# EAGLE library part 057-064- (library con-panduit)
CONNECTOR 64-pin series 057 contact pc board low profile headers
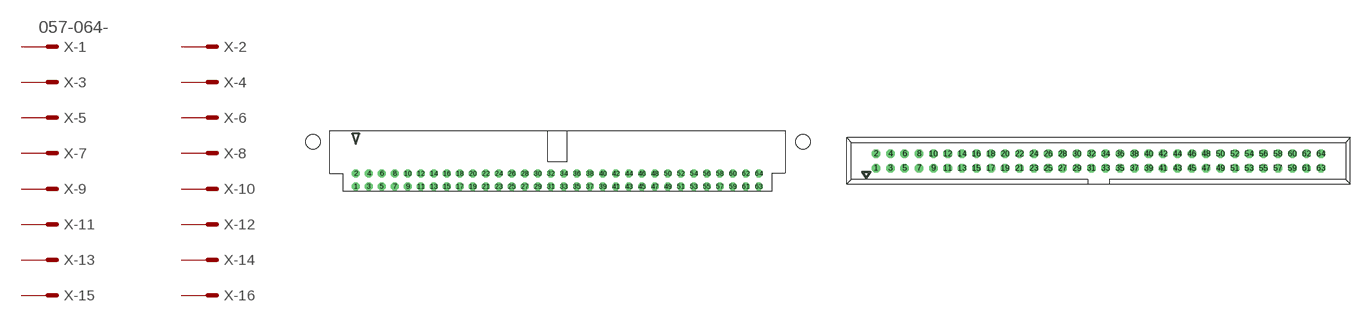
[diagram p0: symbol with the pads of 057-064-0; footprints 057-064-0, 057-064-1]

Designator prefix X; gates -1=MV -2=M -3=M -4=M -5=M -6=M -7=M -8=M -9=M -10=M -11=M -12=M -13=M -14=M -15=M -16=M -17=M -18=M -19=M -20=M -21=M -22=M -23=M -24=M -25=M -26=M -27=M -28=M -29=M -30=M -31=M -32=M -33=M -34=M -35=M -36=M -37=M -38=M -39=M -40=M -41=M -42=M -43=M -44=M -45=M -46=M -47=M -48=M -49=M -50=M -51=M -52=M -53=M -54=M -55=M -56=M -57=M -58=M -59=M -60=M -61=M -62=M -63=M -64=M

## 057-064-0 (OC_FARNELL: unknown; OC_NEWARK: unknown)  [057-064-0]
1  -1:S  pas
2  -2:S  pas
3  -3:S  pas
4  -4:S  pas
5  -5:S  pas
6  -6:S  pas
7  -7:S  pas
8  -8:S  pas
9  -9:S  pas
10  -10:S  pas
11  -11:S  pas
12  -12:S  pas
13  -13:S  pas
14  -14:S  pas
15  -15:S  pas
16  -16:S  pas
17  -17:S  pas
18  -18:S  pas
19  -19:S  pas
20  -20:S  pas
21  -21:S  pas
22  -22:S  pas
23  -23:S  pas
24  -24:S  pas
25  -25:S  pas
26  -26:S  pas
27  -27:S  pas
28  -28:S  pas
29  -29:S  pas
30  -30:S  pas
31  -31:S  pas
32  -32:S  pas
33  -33:S  pas
34  -34:S  pas
35  -35:S  pas
36  -36:S  pas
37  -37:S  pas
38  -38:S  pas
39  -39:S  pas
40  -40:S  pas
41  -41:S  pas
42  -42:S  pas
43  -43:S  pas
44  -44:S  pas
45  -45:S  pas
46  -46:S  pas
47  -47:S  pas
48  -48:S  pas
49  -49:S  pas
50  -50:S  pas
51  -51:S  pas
52  -52:S  pas
53  -53:S  pas
54  -54:S  pas
55  -55:S  pas
56  -56:S  pas
57  -57:S  pas
58  -58:S  pas
59  -59:S  pas
60  -60:S  pas
61  -61:S  pas
62  -62:S  pas
63  -63:S  pas
64  -64:S  pas

## 057-064-1 (OC_FARNELL: unknown; OC_NEWARK: unknown)  [057-064-1]
Pads as for 057-064-0

## Footprint 057-064-0 (pad centres in mm)
CONNECTOR series 057 contact pc board low profile headers angled
drill 1 octagon: 1 -39.37,-5.08; 2 -39.37,-2.54; 3 -36.83,-5.08; 4 -36.83,-2.54; 5 -34.29,-5.08; 6 -34.29,-2.54; 7 -31.75,-5.08; 8 -31.75,-2.54; 9 -29.21,-5.08; 10 -29.21,-2.54; 11 -26.67,-5.08; 12 -26.67,-2.54; 13 -24.13,-5.08; 14 -24.13,-2.54; 15 -21.59,-5.08; 16 -21.59,-2.54; 17 -19.05,-5.08; 18 -19.05,-2.54; 19 -16.51,-5.08; 20 -16.51,-2.54; 21 -13.97,-5.08; 22 -13.97,-2.54; 23 -11.43,-5.08; 24 -11.43,-2.54; 25 -8.89,-5.08; 26 -8.89,-2.54; 27 -6.35,-5.08; 28 -6.35,-2.54; 29 -3.81,-5.08; 30 -3.81,-2.54; 31 -1.27,-5.08; 32 -1.27,-2.54; 33 1.27,-5.08; 34 1.27,-2.54; 35 3.81,-5.08; 36 3.81,-2.54; 37 6.35,-5.08; 38 6.35,-2.54; 39 8.89,-5.08; 40 8.89,-2.54; 41 11.43,-5.08; 42 11.43,-2.54; 43 13.97,-5.08; 44 13.97,-2.54; 45 16.51,-5.08; 46 16.51,-2.54; 47 19.05,-5.08; 48 19.05,-2.54; 49 21.59,-5.08; 50 21.59,-2.54; 51 24.13,-5.08; 52 24.13,-2.54; 53 26.67,-5.08; 54 26.67,-2.54; 55 29.21,-5.08; 56 29.21,-2.54; 57 31.75,-5.08; 58 31.75,-2.54; 59 34.29,-5.08; 60 34.29,-2.54; 61 36.83,-5.08; 62 36.83,-2.54; 63 39.37,-5.08; 64 39.37,-2.54
hole 2.8 at -47.77,3.66
hole 2.8 at 48.02,3.66

## Footprint 057-064-1 (pad centres in mm)
CONNECTOR series 057 contact pc board low profile headers straight
drill 1 octagon: 1 -39.37,-1.27; 2 -39.37,1.27; 3 -36.83,-1.27; 4 -36.83,1.27; 5 -34.29,-1.27; 6 -34.29,1.27; 7 -31.75,-1.27; 8 -31.75,1.27; 9 -29.21,-1.27; 10 -29.21,1.27; 11 -26.67,-1.27; 12 -26.67,1.27; 13 -24.13,-1.27; 14 -24.13,1.27; 15 -21.59,-1.27; 16 -21.59,1.27; 17 -19.05,-1.27; 18 -19.05,1.27; 19 -16.51,-1.27; 20 -16.51,1.27; 21 -13.97,-1.27; 22 -13.97,1.27; 23 -11.43,-1.27; 24 -11.43,1.27; 25 -8.89,-1.27; 26 -8.89,1.27; 27 -6.35,-1.27; 28 -6.35,1.27; 29 -3.81,-1.27; 30 -3.81,1.27; 31 -1.27,-1.27; 32 -1.27,1.27; 33 1.27,-1.27; 34 1.27,1.27; 35 3.81,-1.27; 36 3.81,1.27; 37 6.35,-1.27; 38 6.35,1.27; 39 8.89,-1.27; 40 8.89,1.27; 41 11.43,-1.27; 42 11.43,1.27; 43 13.97,-1.27; 44 13.97,1.27; 45 16.51,-1.27; 46 16.51,1.27; 47 19.05,-1.27; 48 19.05,1.27; 49 21.59,-1.27; 50 21.59,1.27; 51 24.13,-1.27; 52 24.13,1.27; 53 26.67,-1.27; 54 26.67,1.27; 55 29.21,-1.27; 56 29.21,1.27; 57 31.75,-1.27; 58 31.75,1.27; 59 34.29,-1.27; 60 34.29,1.27; 61 36.83,-1.27; 62 36.83,1.27; 63 39.37,-1.27; 64 39.37,1.27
